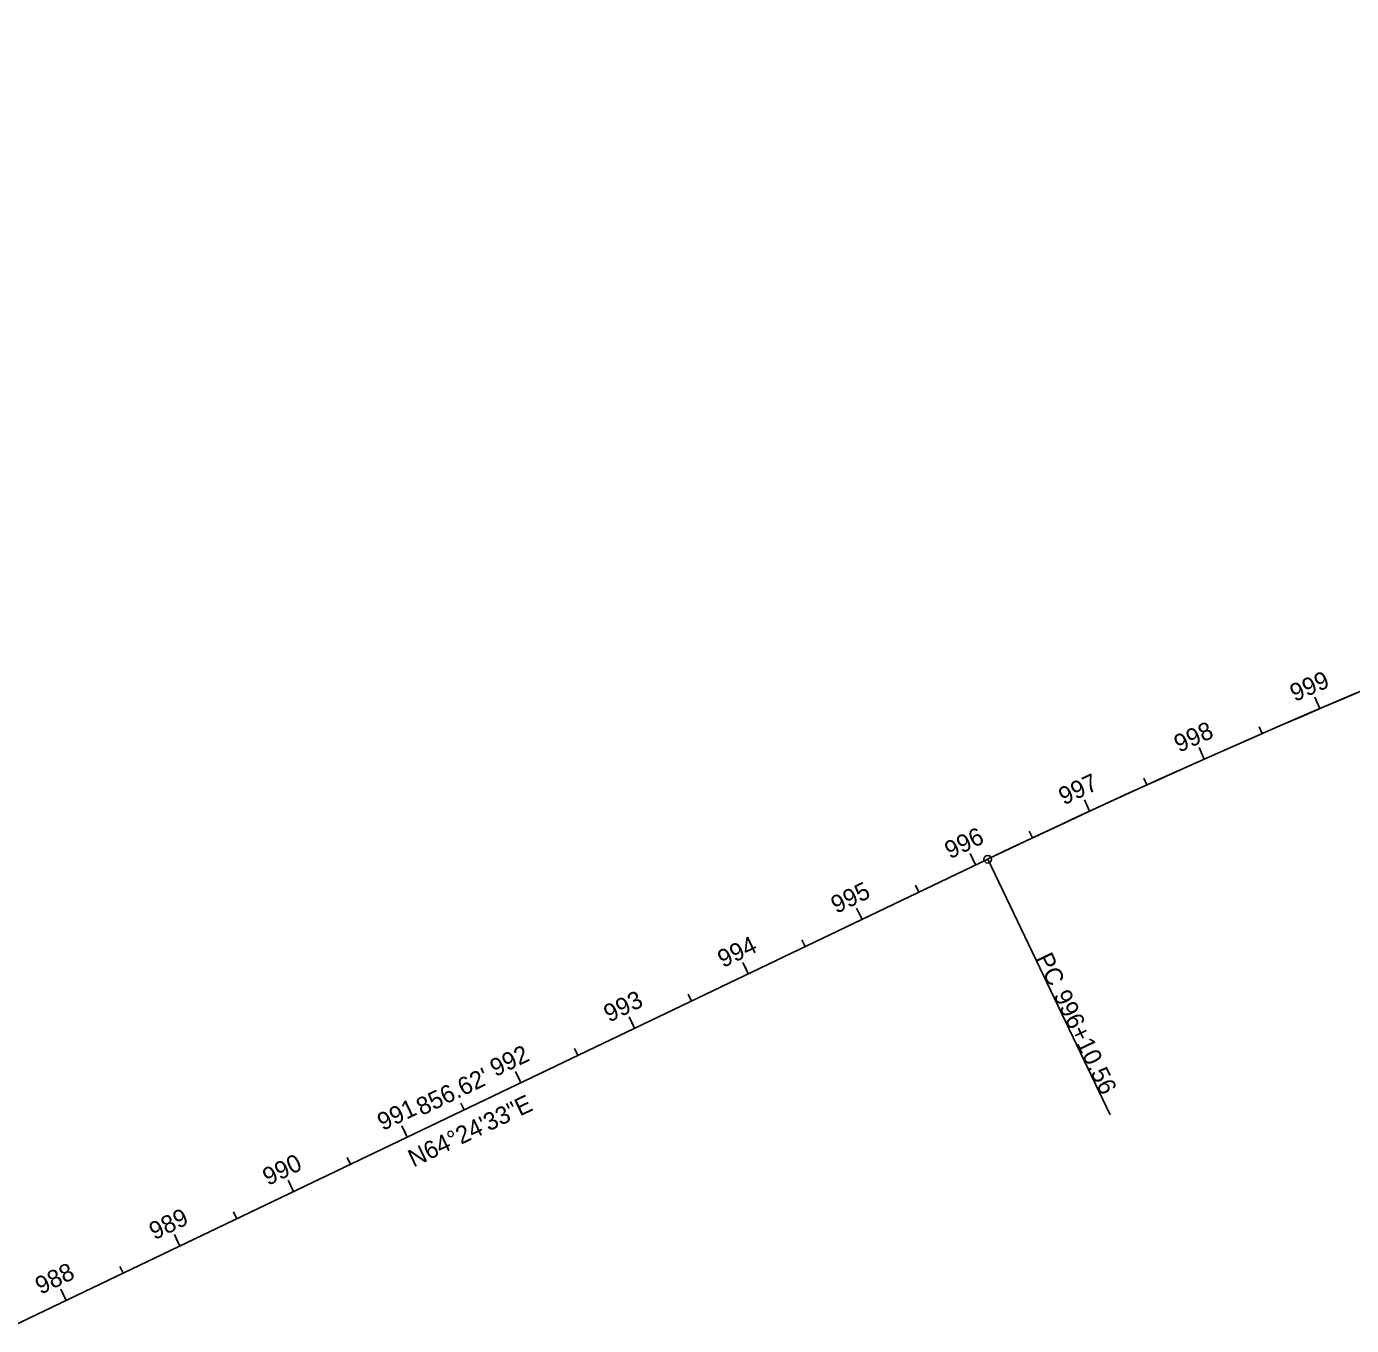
# Model space of a CAD drawing. Extents: x 2192013 to 2197996, y 660216 to 661764.
# Drawn here: x 2193957 to 2195008, y 660716 to 661747 of the extents above; entities that cross this region are included whole.
import ezdxf

# ---------------------------------------------------------------- set-up
doc = ezdxf.new("R2010")
doc.units = 0
for name, color, linetype in [('Default', 7, 'Continuous'), ('GE_X_Alignment', 7, 'Continuous'), ('GE_X_Alignment_1000_Stations', 7, 'Continuous'), ('GE_X_Alignment_100_Stations', 7, 'Continuous'), ('GE_X_Alignment_500_Stations', 7, 'Continuous'), ('SC_Scratch1', 7, 'Continuous')]:
    doc.layers.add(name, color=color, linetype=linetype)

msp = doc.modelspace()

# ---------------------------------------------------------------- linework, layer by layer
at = {"layer": 'Default'}
for centre in [(2194983.1, 661205.3), (2194891.4, 661165.3), (2194800.4, 661123.9), (2194719.5, 661085.8), (2194719.5, 661085.8), (2194719.5, 661085.8), (2194709.9, 661081.3), (2194619.8, 661038.1), (2194619.8, 661038.1), (2194529.6, 660994.9), (2194439.4, 660951.7), (2194349.2, 660908.5), (2194333.2, 660900.8), (2194333.2, 660900.8), (2194333.2, 660900.8), (2194333.2, 660900.8), (2194333.2, 660900.8), (2194333.2, 660900.8), (2194259, 660865.3), (2194168.8, 660822.1), (2194168.8, 660822.1), (2194168.8, 660822.1), (2194078.6, 660778.9), (2193988.4, 660735.7)]:
    msp.add_circle(centre, 0.0000833, dxfattribs=at)
at = {"layer": 'GE_X_Alignment'}
msp.add_line((2193946.9, 660715.8), (2194719.5, 661085.8), dxfattribs=at)
msp.add_line((2193946.9, 660715.8), (2194719.5, 661085.8), dxfattribs=at)
for start in [93.57492, 94.65616]:
    msp.add_arc((2197687.9, 654887.7), 6872.3, start, 115.59075, dxfattribs=at)
at = {"layer": 'GE_X_Alignment_1000_Stations'}
for p, q in [((2194719.5, 661085.8), (2194816.7, 660882.9)), ((2194619.8, 661038.1), (2194617.2, 661043.5)), ((2194168.8, 660822.1), (2194164.5, 660831.1))]:
    msp.add_line(p, q, dxfattribs=at)
msp.add_circle((2194719.5, 661085.8), 3, dxfattribs=at)
at = {"layer": 'GE_X_Alignment_100_Stations'}
for p, q in [((2194983.1, 661205.3), (2194979.1, 661214.5)), ((2194937.2, 661185.5), (2194934.8, 661191)), ((2194891.4, 661165.3), (2194887.4, 661174.4)), ((2194845.8, 661144.8), (2194843.3, 661150.2)), ((2194800.4, 661123.9), (2194796.2, 661133)), ((2194755.1, 661102.8), (2194752.5, 661108.2)), ((2194709.9, 661081.3), (2194705.6, 661090.3)), ((2194719.5, 661085.8), (2194816.7, 660882.9)), ((2194664.8, 661059.7), (2194662.3, 661065.1)), ((2194619.8, 661038.1), (2194615.4, 661047.1)), ((2194574.7, 661016.5), (2194572.1, 661021.9)), ((2194529.6, 660994.9), (2194525.2, 661003.9)), ((2194484.5, 660973.3), (2194481.9, 660978.7)), ((2194439.4, 660951.7), (2194435.1, 660960.7)), ((2194394.3, 660930.1), (2194391.7, 660935.5)), ((2194349.2, 660908.5), (2194344.9, 660917.5)), ((2194304.1, 660886.9), (2194301.5, 660892.3)), ((2194259, 660865.3), (2194254.7, 660874.3)), ((2194213.9, 660843.7), (2194211.3, 660849.1)), ((2194168.8, 660822.1), (2194164.5, 660831.1)), ((2194123.7, 660800.5), (2194121.1, 660805.9)), ((2194078.6, 660778.9), (2194074.3, 660787.9)), ((2194033.5, 660757.3), (2194030.9, 660762.7)), ((2193988.4, 660735.7), (2193984.1, 660744.7))]:
    msp.add_line(p, q, dxfattribs=at)
msp.add_circle((2194719.5, 661085.8), 3, dxfattribs=at)
at = {"layer": 'GE_X_Alignment_500_Stations'}
for p, q in [((2194983.1, 661205.3), (2194980.7, 661210.8)), ((2194891.4, 661165.3), (2194889, 661170.8)), ((2194800.4, 661123.9), (2194797.9, 661129.4)), ((2194709.9, 661081.3), (2194707.3, 661086.7)), ((2194719.5, 661085.8), (2194816.7, 660882.9)), ((2194619.8, 661038.1), (2194615.4, 661047.1)), ((2194529.6, 660994.9), (2194527, 661000.3)), ((2194439.4, 660951.7), (2194436.8, 660957.1)), ((2194349.2, 660908.5), (2194346.6, 660913.9)), ((2194259, 660865.3), (2194256.4, 660870.7)), ((2194168.8, 660822.1), (2194164.5, 660831.1)), ((2194078.6, 660778.9), (2194076, 660784.3)), ((2193988.4, 660735.7), (2193985.8, 660741.1))]:
    msp.add_line(p, q, dxfattribs=at)
msp.add_circle((2194719.5, 661085.8), 3, dxfattribs=at)
at = {"layer": 'SC_Scratch1'}
msp.add_line((2193946.9, 660715.8), (2194719.5, 661085.8), dxfattribs=at)

# ---------------------------------------------------------------- texts
at = {"layer": 'GE_X_Alignment_1000_Stations'}
for s, rotation, p in [('PC', 295.5908, (2194757.3, 661007.4)), ('996+10.56', 295.5908, (2194771.4, 660978)), ("856.62'", 25.5908, (2194270.4, 660882)), ('N64°24\'33"E', 25.5908, (2194263.9, 660841.1)), ('990', 25.5908, (2194148.5, 660826.5))]:
    msp.add_text(s, height=14, rotation=rotation, dxfattribs=at).set_placement(p)
at = {"layer": 'GE_X_Alignment_100_Stations'}
for s, rotation, p in [('999', 23.1777, (2194963.1, 661210.6)), ('998', 24.0114, (2194871.3, 661170.2)), ('997', 24.8451, (2194779.9, 661128.5)), ('996', 25.5908, (2194689.6, 661085.7)), ('995', 25.5908, (2194599.4, 661042.4)), ('994', 25.5908, (2194509.5, 660999.4)), ('PC', 295.5908, (2194757.3, 661007.4)), ('993', 25.5908, (2194419.1, 660956.1)), ('996+10.56', 295.5908, (2194771.4, 660978)), ('992', 25.5908, (2194328.9, 660912.9)), ("856.62'", 25.5908, (2194270.4, 660882)), ('991', 25.5908, (2194239.5, 660870.1)), ('N64°24\'33"E', 25.5908, (2194263.9, 660841.1)), ('990', 25.5908, (2194148.5, 660826.5)), ('989', 25.5908, (2194058.4, 660783.4)), ('988', 25.5908, (2193968.1, 660740.1))]:
    msp.add_text(s, height=14, rotation=rotation, dxfattribs=at).set_placement(p)
at = {"layer": 'GE_X_Alignment_500_Stations'}
for s, rotation, p in [('995', 25.5908, (2194599.4, 661042.4)), ('PC', 295.5908, (2194757.3, 661007.4)), ('996+10.56', 295.5908, (2194771.4, 660978)), ("856.62'", 25.5908, (2194270.4, 660882)), ('N64°24\'33"E', 25.5908, (2194263.9, 660841.1)), ('990', 25.5908, (2194148.5, 660826.5))]:
    msp.add_text(s, height=14, rotation=rotation, dxfattribs=at).set_placement(p)

doc.saveas('drawing.dxf')
